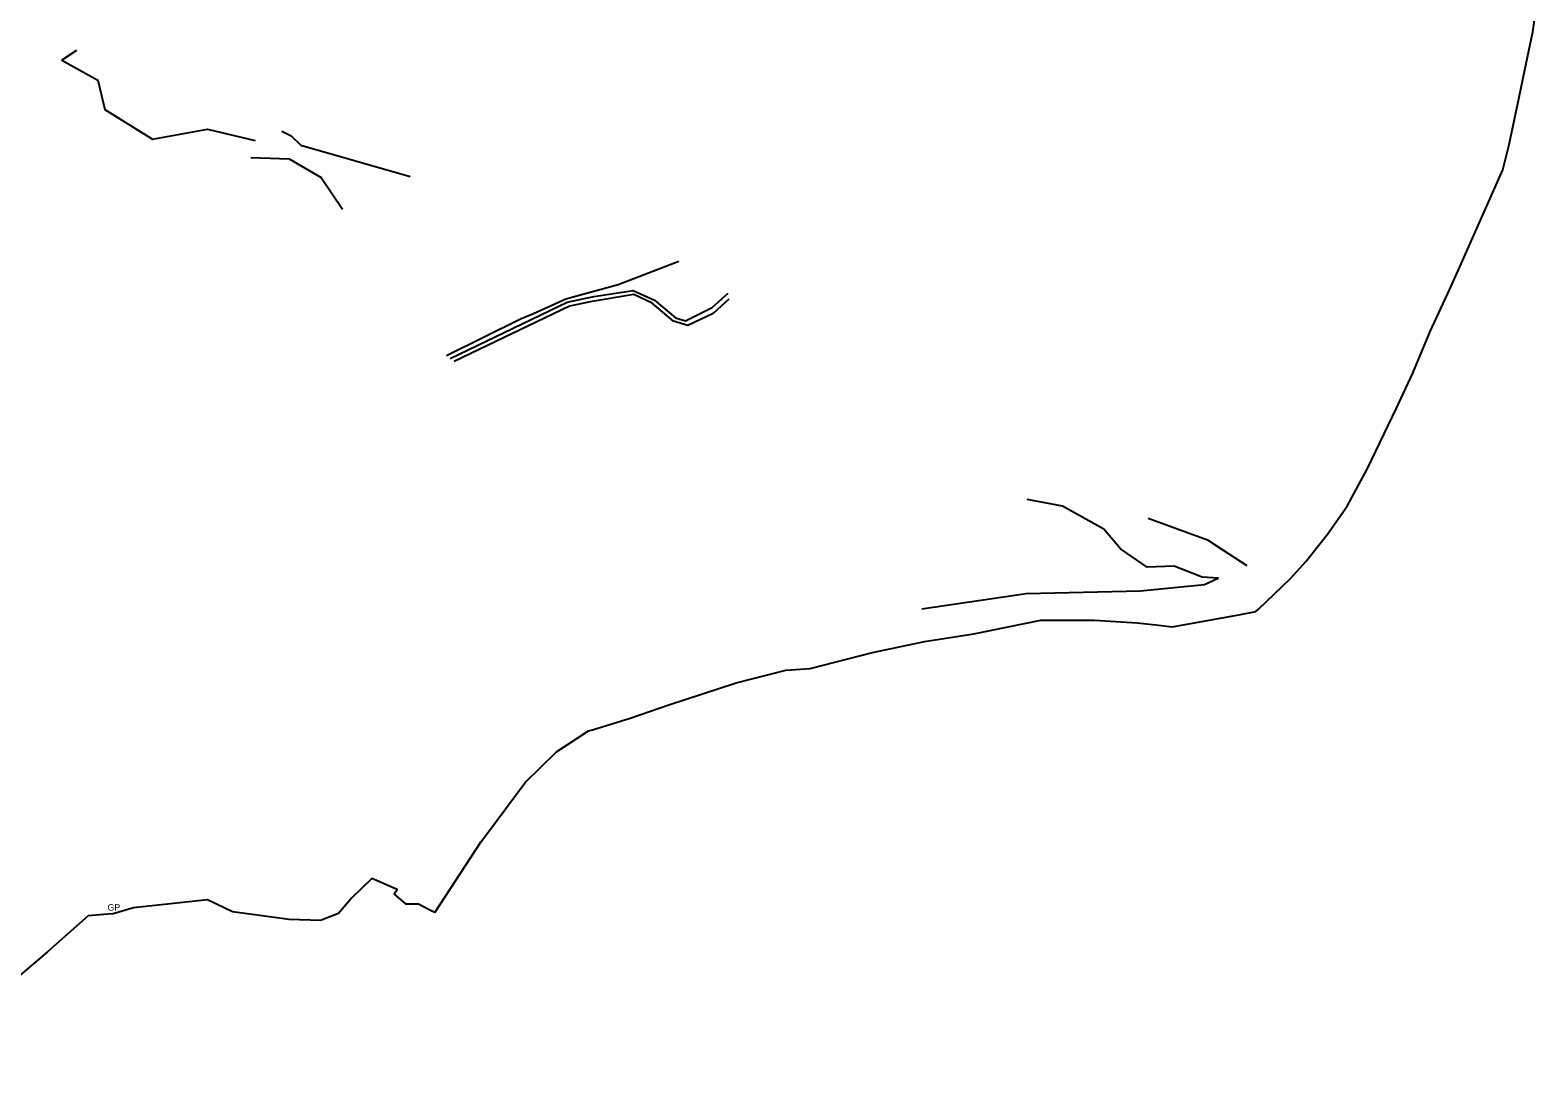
# Model space of a CAD drawing. Extents: x -587103 to -585114, y -1103460 to -1100918.
# Drawn here: x -586156 to -585236, y -1103225 to -1102590 of the extents above; entities that cross this region are included whole.
import ezdxf

# ---------------------------------------------------------------- set-up
doc = ezdxf.new("R2010")
doc.units = 0
for name, color, linetype in [('LES_ZV', 7, 'Continuous'), ('OVNE_POP', 7, 'Continuous'), ('OVNE_SET', 7, 'Continuous')]:
    doc.layers.add(name, color=color, linetype=linetype)

msp = doc.modelspace()

# ---------------------------------------------------------------- linework, layer by layer
at = {"layer": 'LES_ZV'}
for points in [[(-586127.84, -1102602.67), (-586136.91, -1102608.7), (-586114.88, -1102620.93), (-586110.54, -1102638.7), (-586081.63, -1102656.76), (-586048.04, -1102650.65), (-586018.84, -1102657.55)], [(-586002.72, -1102651.88), (-585996.96, -1102654.77), (-585990.96, -1102660.48), (-585924.35, -1102679.64)], [(-586021.63, -1102668.1), (-585998.16, -1102668.82), (-585978.7, -1102680.18), (-585965.66, -1102699.47)], [(-585760.51, -1102731.38), (-585797.43, -1102745.76), (-585829.4, -1102754.52), (-585849.04, -1102763.44), (-585857.12, -1102766.74), (-585902.24, -1102788.96)], [(-585899.96, -1102790.65), (-585828.56, -1102756.33), (-585812.24, -1102752.72), (-585796.17, -1102750.35), (-585788.33, -1102749.2), (-585775.19, -1102755.01), (-585762.47, -1102765.84), (-585756.33, -1102767.59), (-585740.13, -1102759.49), (-585730.24, -1102750.82)], [(-585729.93, -1102754.43), (-585739.41, -1102763.29), (-585754.88, -1102770.45), (-585763.68, -1102767.92), (-585776.66, -1102756.82), (-585787.87, -1102751.64), (-585814.56, -1102756.15), (-585827.12, -1102758.79), (-585897.51, -1102792.48)], [(-585612.2, -1102943.32), (-585548.43, -1102933.96), (-585478.79, -1102932.33), (-585439.81, -1102928.48), (-585431.42, -1102924.74), (-585441.06, -1102924.12), (-585458.23, -1102917.27), (-585474.7, -1102918.05), (-585491.03, -1102906.76), (-585501.06, -1102894.74), (-585526.33, -1102880.8), (-585547.99, -1102876.76)], [(-585474.19, -1102888.02), (-585437.96, -1102901.29), (-585428.96, -1102907.13), (-585413.88, -1102916.92)]]:
    msp.add_lwpolyline(points, dxfattribs=at)
at = {"layer": 'OVNE_SET'}
for points in [[(-585909.37, -1103128.69), (-585881.02, -1103085.34), (-585877.14, -1103080.16), (-585854.13, -1103049.39), (-585835.07, -1103030.55), (-585815.44, -1103017.83), (-585813.05, -1103017.1), (-585798.61, -1103012.65), (-585790.22, -1103010.07), (-585766.45, -1103001.99), (-585725.4, -1102988.56), (-585695.2, -1102980.73), (-585680.23, -1102979.73), (-585642.2, -1102969.91), (-585613.32, -1102963.91), (-585610.47, -1102963.32), (-585580.47, -1102958.64), (-585539.49, -1102950.28), (-585539, -1102950.28), (-585508.26, -1102950.2), (-585506.88, -1102950.2), (-585480.87, -1102951.89), (-585467.53, -1102953.43), (-585459.37, -1102954.37), (-585418.78, -1102946.96), (-585408.34, -1102945.06), (-585406.7, -1102943.48), (-585387.35, -1102924.78), (-585377.76, -1102914.26), (-585370.95, -1102905.68), (-585368.52, -1102902.62), (-585364.78, -1102897.91), (-585352.6, -1102880.64), (-585340.21, -1102857.81), (-585322.65, -1102821), (-585312.71, -1102799.62), (-585302.07, -1102774.24), (-585290.36, -1102748.67), (-585284, -1102734.78), (-585257.74, -1102675.58), (-585253.9, -1102660.07), (-585247.85, -1102631.29), (-585244.34, -1102614.63), (-585239.5, -1102591.28), (-585236.36, -1102569.44)], [(-585909.37, -1103128.69), (-585912.31, -1103127.2), (-585919.33, -1103123.65), (-585926.85, -1103123.61), (-585934.1, -1103117.22), (-585932.27, -1103114.57), (-585947.69, -1103107.92), (-585959.98, -1103119.65), (-585967.97, -1103129.28), (-585979.01, -1103133.58), (-585998.08, -1103132.96), (-586032.71, -1103128.16), (-586048.06, -1103120.93), (-586093.11, -1103125.83), (-586105.56, -1103129.45), (-586108.85, -1103129.57), (-586120.87, -1103130.68)], [(-586120.87, -1103130.68), (-586145.56, -1103152.65), (-586185.38, -1103186.47), (-586190.95, -1103190.51), (-586221.48, -1103211.25), (-586240.63, -1103225.24)]]:
    msp.add_lwpolyline(points, dxfattribs=at)

# ---------------------------------------------------------------- texts
at = {"layer": 'OVNE_POP'}
msp.add_text('GP', height=4, dxfattribs=at).set_placement((-586108.99, -1103127.5))

doc.saveas('drawing.dxf')
